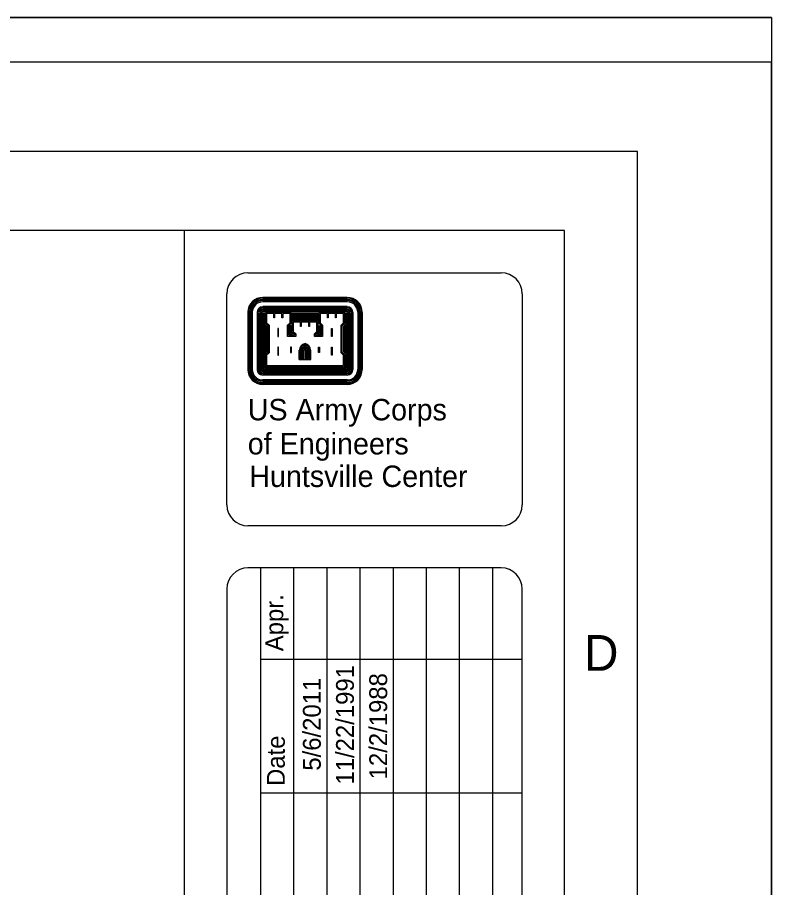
# Model space of a CAD drawing. Extents: x -0.04 to 2.79, y -0.02 to 1.81.
# Drawn here: x 2.4399 to 2.7917, y 1.4065 to 1.8125 of the extents above; entities that cross this region are included whole.
import ezdxf

# ---------------------------------------------------------------- set-up
doc = ezdxf.new("R2010")
doc.units = 0
for name, color, linetype in [('G-ANNO-NPLT', 7, 'Continuous'), ('G-ANNO-PLOT', 7, 'Continuous'), ('G-ANNO-TTLB', 7, 'Continuous')]:
    doc.layers.add(name, color=color, linetype=linetype)

msp = doc.modelspace()

# ---------------------------------------------------------------- linework, layer by layer
at = {"layer": 'G-ANNO-NPLT'}
msp.add_lwpolyline([(-0.04167, 1.8125), (2.79167, 1.8125), (2.79167, -0.02083), (-0.04167, -0.02083)], close=True, dxfattribs=at)
at = {"layer": 'G-ANNO-PLOT'}
for q in [(-0.04167, 1.8125), (2.79167, -0.02083)]:
    msp.add_line((2.79167, 1.8125), q, dxfattribs=at)
msp.add_lwpolyline([(0, 0), (2.79167, 0), (2.79167, 1.79167), (0, 1.79167)], close=True, dxfattribs=at)
at = {"layer": 'G-ANNO-TTLB'}
for p, q in [((2.51784, 0.08028), (2.51784, 1.71305)), ((2.59375, 1.68188), (2.55434, 1.68188)), ((2.59375, 1.68147), (2.55434, 1.68147)), ((2.59375, 1.6809), (2.55434, 1.6809)), ((2.59375, 1.68036), (2.55434, 1.68036)), ((2.59375, 1.67979), (2.55434, 1.67979)), ((2.59375, 1.67758), (2.55434, 1.67758)), ((2.59375, 1.67696), (2.55434, 1.67696)), ((2.54733, 1.67487), (2.54733, 1.64825)), ((2.54774, 1.67487), (2.54774, 1.64825)), ((2.54835, 1.67487), (2.54835, 1.64825)), ((2.54889, 1.67487), (2.54889, 1.64825)), ((2.54942, 1.67487), (2.54942, 1.64825)), ((2.55172, 1.67487), (2.55172, 1.64825)), ((2.55229, 1.67487), (2.55229, 1.64825)), ((2.55282, 1.67487), (2.55282, 1.64825)), ((2.5534, 1.67487), (2.5534, 1.64825)), ((2.55397, 1.67487), (2.55397, 1.64825)), ((2.59375, 1.67639), (2.55434, 1.67639)), ((2.59375, 1.67581), (2.55434, 1.67581)), ((2.59375, 1.67528), (2.55434, 1.67528)), ((2.5545, 1.67487), (2.5545, 1.64842)), ((2.55508, 1.67487), (2.55508, 1.64903)), ((2.56791, 1.67471), (2.58009, 1.67471)), ((2.56791, 1.67417), (2.58009, 1.67417)), ((2.56791, 1.67368), (2.58009, 1.67368)), ((2.56791, 1.67307), (2.58009, 1.67307)), ((2.59301, 1.67487), (2.59301, 1.64903)), ((2.59355, 1.67487), (2.59355, 1.64842)), ((2.59412, 1.67487), (2.59412, 1.64825)), ((2.59469, 1.67487), (2.59469, 1.64825)), ((2.59527, 1.67487), (2.59527, 1.64825)), ((2.5958, 1.67487), (2.5958, 1.64825)), ((2.59638, 1.67487), (2.59638, 1.64825)), ((2.59863, 1.67487), (2.59863, 1.64825)), ((2.59921, 1.67487), (2.59921, 1.64825)), ((2.59974, 1.67487), (2.59974, 1.64825)), ((2.60031, 1.67487), (2.60031, 1.64825)), ((2.60072, 1.67487), (2.60072, 1.64825)), ((2.55553, 1.66921), (2.55553, 1.65559)), ((2.56791, 1.67253), (2.58009, 1.67253)), ((2.56791, 1.67196), (2.58009, 1.67196)), ((2.56791, 1.67138), (2.58009, 1.67138)), ((2.59252, 1.66917), (2.59252, 1.65568)), ((2.5561, 1.66864), (2.5561, 1.65625)), ((2.59203, 1.66864), (2.59203, 1.65625)), ((2.57136, 1.65285), (2.57136, 1.65719)), ((2.57193, 1.65285), (2.57193, 1.65719)), ((2.57251, 1.65285), (2.57251, 1.65719)), ((2.57308, 1.65285), (2.57308, 1.65719)), ((2.5737, 1.65285), (2.5737, 1.65719)), ((2.57443, 1.65285), (2.57443, 1.65719)), ((2.57497, 1.65285), (2.57497, 1.65719)), ((2.57554, 1.65285), (2.57554, 1.65719)), ((2.57612, 1.65285), (2.57612, 1.65719)), ((2.57669, 1.65285), (2.57669, 1.65719)), ((2.57136, 1.65285), (2.57669, 1.65285)), ((2.59301, 1.64903), (2.55508, 1.64903)), ((2.59375, 1.64784), (2.55434, 1.64784)), ((2.59375, 1.64731), (2.55434, 1.64731)), ((2.59375, 1.64674), (2.55434, 1.64674)), ((2.59375, 1.64616), (2.55434, 1.64616)), ((2.59375, 1.64563), (2.55434, 1.64563)), ((2.59355, 1.64842), (2.5545, 1.64842)), ((2.59375, 1.64333), (2.55434, 1.64333)), ((2.59375, 1.64276), (2.55434, 1.64276)), ((2.59375, 1.64227), (2.55434, 1.64227)), ((2.59375, 1.64169), (2.55434, 1.64169)), ((2.59375, 1.64124), (2.55434, 1.64124)), ((2.55319, 1.55567), (2.55319, 1.15168)), ((2.56861, 1.55567), (2.56861, 1.15168)), ((2.58415, 1.55567), (2.58415, 1.15168)), ((2.59962, 1.55567), (2.59962, 1.15168)), ((2.61512, 1.55567), (2.61512, 1.15168)), ((2.63058, 1.55567), (2.63058, 1.15168)), ((2.646, 1.55567), (2.646, 1.15168)), ((2.66154, 1.55567), (2.66154, 1.15168)), ((2.55319, 1.51302), (2.67536, 1.51302)), ((2.55319, 1.45069), (2.67536, 1.45069))]:
    msp.add_line(p, q, dxfattribs=at)
for points in [[(0.08333, 0.04167), (2.72917, 0.04167), (2.72917, 1.75), (0.2515, 1.75)], [(0.11656, 0.08028), (2.69501, 0.08028), (2.69501, 1.71305), (0.11656, 1.71305)], [(2.54741, 1.69337), (2.66552, 1.69337)], [(2.53757, 1.5851), (2.53757, 1.68352)], [(2.67536, 1.68352), (2.67536, 1.5851)], [(2.55553, 1.67487), (2.55553, 1.66978), (2.55668, 1.66864), (2.55668, 1.65625), (2.55553, 1.65506), (2.55553, 1.6494), (2.59256, 1.6494), (2.59256, 1.65506), (2.59137, 1.65625), (2.59137, 1.66864), (2.59256, 1.66978), (2.59256, 1.67487), (2.58772, 1.67487), (2.58387, 1.67487), (2.58042, 1.67487), (2.58042, 1.66978), (2.58165, 1.66864), (2.58165, 1.66417), (2.57895, 1.66417), (2.57895, 1.66458), (2.58009, 1.66572), (2.58009, 1.67077), (2.57517, 1.67077), (2.57144, 1.67077), (2.56791, 1.67077), (2.56791, 1.66572), (2.5691, 1.66458), (2.5691, 1.66417), (2.56644, 1.66417), (2.56644, 1.66864), (2.56763, 1.66978), (2.56763, 1.67487), (2.56262, 1.67487), (2.55889, 1.67487), (2.55553, 1.67487)], [(2.5561, 1.67434), (2.5561, 1.67003), (2.55725, 1.66884), (2.55725, 1.65601), (2.5561, 1.65486), (2.5561, 1.65002), (2.59203, 1.65002), (2.59203, 1.65486), (2.59088, 1.65601), (2.59088, 1.66884), (2.59203, 1.67003), (2.59203, 1.67434), (2.58858, 1.67434), (2.58858, 1.67233), (2.58826, 1.67233), (2.58826, 1.67434), (2.58481, 1.67434), (2.58481, 1.67233), (2.58448, 1.67233), (2.58448, 1.67434), (2.58104, 1.67434), (2.58104, 1.67003), (2.58219, 1.66884), (2.58219, 1.66355), (2.57841, 1.66355), (2.57841, 1.66482), (2.57956, 1.66593), (2.57956, 1.67028), (2.57612, 1.67028), (2.57612, 1.66823), (2.57575, 1.66823), (2.57575, 1.67028), (2.5723, 1.67028), (2.5723, 1.66823), (2.57193, 1.66823), (2.57193, 1.67028), (2.56853, 1.67028), (2.56853, 1.66593), (2.56968, 1.66482), (2.56968, 1.66355), (2.56582, 1.66355), (2.56582, 1.66884), (2.56705, 1.67003), (2.56705, 1.67434), (2.56361, 1.67434), (2.56361, 1.67233), (2.56328, 1.67233), (2.56328, 1.67434), (2.55979, 1.67434), (2.55979, 1.67233), (2.55951, 1.67233), (2.55951, 1.67434), (2.5561, 1.67434)], [(2.56135, 1.66741), (2.56135, 1.66355), (2.56168, 1.66355), (2.56168, 1.66741), (2.56135, 1.66741)], [(2.56734, 1.66872), (2.56697, 1.66839), (2.56697, 1.66466), (2.5682, 1.66466), (2.56738, 1.66552), (2.56738, 1.66876)], [(2.58071, 1.66872), (2.58104, 1.66839), (2.58104, 1.66466), (2.57989, 1.66466), (2.58067, 1.66552), (2.58067, 1.66876)], [(2.5867, 1.66741), (2.5867, 1.66355), (2.58633, 1.66355), (2.58633, 1.66741), (2.5867, 1.66741)], [(2.56135, 1.65867), (2.56135, 1.6549), (2.56168, 1.6549), (2.56168, 1.65867), (2.56135, 1.65867)], [(2.5673, 1.65867), (2.5673, 1.65609), (2.56767, 1.65609), (2.56767, 1.65867), (2.5673, 1.65867)], [(2.58071, 1.65867), (2.58071, 1.65609), (2.58038, 1.65609), (2.58038, 1.65867), (2.58071, 1.65867)], [(2.5867, 1.65867), (2.5867, 1.6549), (2.58633, 1.6549), (2.58633, 1.65867), (2.5867, 1.65867)], [(2.66552, 1.57526), (2.54741, 1.57526)], [(2.66552, 1.55567), (2.54741, 1.55567)], [(2.53757, 1.54583), (2.53757, 1.16152)], [(2.67536, 1.16152), (2.67536, 1.54583)]]:
    msp.add_lwpolyline(points, dxfattribs=at)
for centre, major_axis, start_param, end_param in [((2.54741, 1.6835), (-0.00984, 0), 4.712389, 6.283185), ((2.66553, 1.6835), (-0.00984, 0), 3.141593, 4.712389), ((2.5543, 1.6749), (-0.00696, 0), 4.712389, 6.283185), ((2.5543, 1.6749), (-0.00656, 0), 4.712389, 6.283185), ((2.59376, 1.6749), (-0.00696, 0), 3.141593, 4.712389), ((2.59376, 1.6749), (0.00656, 0), 0, 1.570796), ((2.5543, 1.6749), (-0.006, 0), 4.712389, 6.283185), ((2.5543, 1.6749), (-0.00543, 0), 4.712389, 6.283185), ((2.5543, 1.6749), (-0.00487, 0), 4.712389, 6.283185), ((2.5543, 1.6749), (-0.00261, 0), 4.712389, 6.283185), ((2.5543, 1.6749), (-0.00205, 0), 4.712389, 6.283185), ((2.59376, 1.6749), (0.006, 0), 0, 1.570796), ((2.59376, 1.6749), (0.00543, 0), 0, 1.570796), ((2.59376, 1.6749), (0.00487, 0), 0, 1.570796), ((2.59376, 1.6749), (-0.00261, 0), 3.141593, 4.712389), ((2.59376, 1.6749), (-0.00205, 0), 3.141593, 4.712389), ((2.5543, 1.6749), (-0.00148, 0), 4.712389, 6.283185), ((2.5543, 1.6749), (0.000919, 0), 1.570796, 3.141593), ((2.5543, 1.6749), (-0.000355, 0), 4.712389, 6.283185), ((2.59376, 1.6749), (-0.00148, 0), 3.141593, 4.712389), ((2.59376, 1.6749), (-0.000919, 0), 3.141593, 4.712389), ((2.59376, 1.6749), (-0.000355, 0), 3.141593, 4.712389), ((2.575, 1.65692), (0.00361, 0), 1.844255, 3.072783), ((2.575, 1.65692), (-0.00304, 0), 4.947481, 6.214375), ((2.575, 1.65692), (-0.00248, 0), 4.947481, 6.214375), ((2.575, 1.65692), (-0.00192, 0), 4.947481, 6.214375), ((2.57306, 1.65692), (0.00135, 0), 0.06881, 1.335704), ((2.57306, 1.65692), (0.00192, 0), 0.06881, 1.335704), ((2.57306, 1.65692), (-0.00248, 0), 3.210403, 4.477297), ((2.575, 1.65692), (-0.00135, 0), 4.947481, 6.214375), ((2.57306, 1.65692), (0.00304, 0), 0.06881, 1.335704), ((2.57306, 1.65692), (0.00361, 0), 0.06881, 1.298435), ((2.5543, 1.64821), (0.00696, 0), 3.141593, 4.712389), ((2.5543, 1.64821), (0.00656, 0), 3.141593, 4.712389), ((2.5543, 1.64821), (-0.006, 0), 0, 1.570796), ((2.5543, 1.64821), (0.00543, 0), 3.141593, 4.712389), ((2.5543, 1.64821), (0.00487, 0), 3.141593, 4.712389), ((2.5543, 1.64821), (0.00261, 0), 3.141593, 4.712389), ((2.5543, 1.64821), (0.00205, 0), 3.141593, 4.712389), ((2.5543, 1.64821), (0.00148, 0), 3.141593, 4.712389), ((2.5543, 1.64821), (0.000919, 0), 3.141593, 4.712389), ((2.5543, 1.64821), (0.000355, 0), 3.141593, 4.712389), ((2.59376, 1.64821), (0.00696, 0), 4.712389, 6.283185), ((2.59376, 1.64821), (0.00261, 0), 4.712389, 6.283185), ((2.59376, 1.64821), (0.00205, 0), 4.712389, 6.283185), ((2.59376, 1.64821), (0.00148, 0), 4.712389, 6.283185), ((2.59376, 1.64821), (0.000919, 0), 4.712389, 6.283185), ((2.59376, 1.64821), (0.000355, 0), 4.712389, 6.283185), ((2.59376, 1.64821), (0.00487, 0), 4.712389, 6.283185), ((2.59376, 1.64821), (0.00543, 0), 4.712389, 6.283185), ((2.59376, 1.64821), (0.006, 0), 4.712389, 6.283185), ((2.59376, 1.64821), (0.00656, 0), 4.712389, 6.283185), ((2.54741, 1.58508), (-0.00984, 0), 0, 1.570796), ((2.66553, 1.58508), (0.00984, 0), 4.712389, 6.283185), ((2.54741, 1.54581), (-0.00984, 0), 4.712389, 6.281588), ((2.66552, 1.54581), (-0.00984, 0), 3.141593, 4.712389)]:
    msp.add_ellipse(centre, major_axis=major_axis, ratio=0.999936, start_param=start_param, end_param=end_param, dxfattribs=at)

# ---------------------------------------------------------------- texts
for s, height, p in [('US Army Corps', 0.01, (2.54733, 1.62448)), ('of Engineers', 0.01, (2.54733, 1.60859)), ('Huntsville Center', 0.01, (2.54802, 1.59339)), ('D', 0.01667, (2.70415, 1.50763)), ('D', 0.01667, (2.70415, 1.50763))]:
    msp.add_text(s, height=height, dxfattribs=at).set_placement(p)
for s, p in [('Appr.', (2.56389, 1.51675)), ('11/22/1991', (2.59684, 1.45454)), ('5/6/2011', (2.58138, 1.46102)), ('12/2/1988', (2.61234, 1.45697)), ('Date', (2.56459, 1.45389))]:
    msp.add_text(s, height=0.008333, rotation=90, dxfattribs=at).set_placement(p)

doc.saveas('drawing.dxf')
